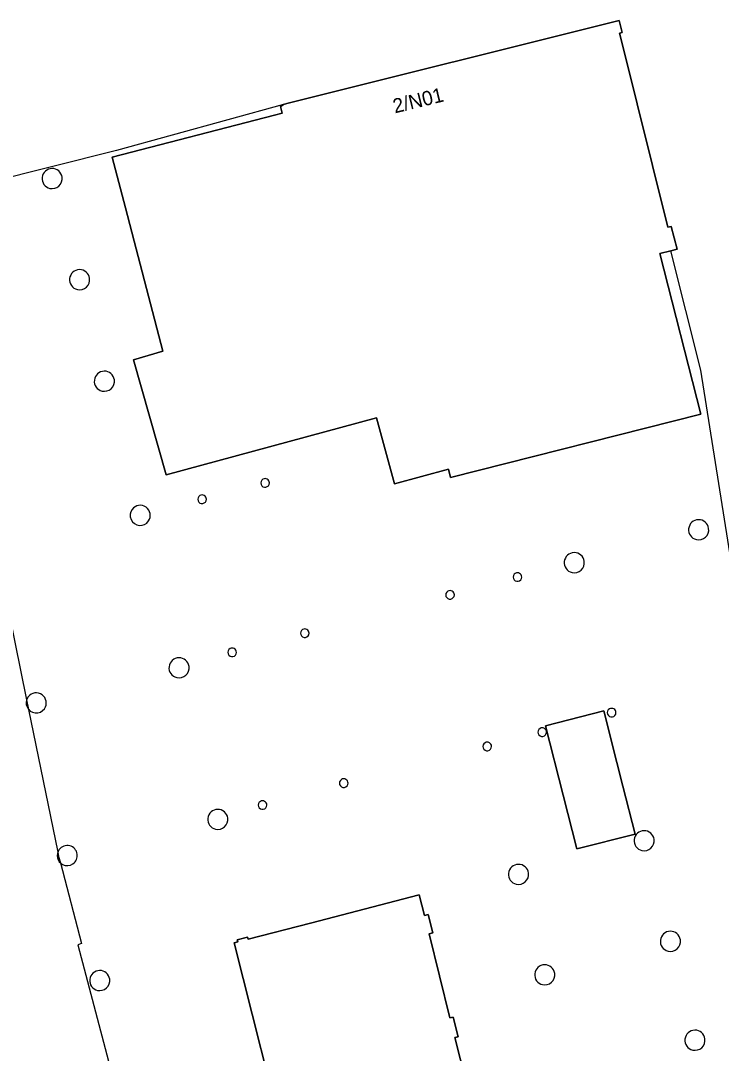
# Model space of a CAD drawing. Extents: x 160806 to 161707, y 383696 to 384148.
# Drawn here: x 161282.3 to 161331, y 383992.9 to 384064.8 of the extents above; entities that cross this region are included whole.
import ezdxf

# ---------------------------------------------------------------- set-up
doc = ezdxf.new("R2010")
doc.units = 0
for name, color, linetype in [('IMGEO_Erf', 7, 'Continuous'), ('IMGEO_Pand', 7, 'Continuous'), ('IMGEO_Pand_nummerreeks', 7, 'Continuous'), ('IMGEO_Pand_overbouw', 7, 'Continuous')]:
    doc.layers.add(name, color=color, linetype=linetype)

msp = doc.modelspace()

# ---------------------------------------------------------------- linework, layer by layer
at = {"layer": 'IMGEO_Erf'}
for points in [[(161329.552, 384037.396), (161312.15, 384032.996), (161312.003, 384033.577), (161308.24, 384032.557), (161306.994, 384037.151), (161292.363, 384033.183), (161290.108, 384041.184), (161292.135, 384041.772), (161290.281, 384048.897), (161289.537, 384051.757), (161288.622, 384055.273), (161299.916, 384058.201), (161300.442, 384058.338), (161300.327, 384058.807), (161300.359, 384058.83), (161300.535, 384058.932), (161300.766, 384059.009), (161323.868, 384064.767), (161324.075, 384063.942), (161323.889, 384063.895), (161324.046, 384063.267), (161327.253, 384050.405), (161327.487, 384050.462), (161327.896, 384048.869), (161327.455, 384048.758), (161326.709, 384048.571)], [(161322.794, 384016.755), (161323.71, 384013.167), (161324.13, 384011.53), (161324.988, 384008.199), (161320.919, 384007.16), (161319.972, 384010.899), (161318.753, 384015.717)], [(161310.919, 384001.335), (161310.658, 384001.268), (161312.108, 383995.404), (161312.338, 383995.464), (161312.682, 383994.096), (161312.451, 383994.037), (161313.62, 383989.378), (161313.677, 383989.154), (161313.593, 383989.134), (161313.129, 383989.019), (161300.843, 383985.84), (161297.111, 384000.629), (161297.354, 384000.692), (161297.319, 384000.838), (161298.032, 384001.03), (161298.073, 384000.878), (161302.412, 384002.002), (161309.96, 384003.959), (161310.329, 384002.536), (161310.591, 384002.604)]]:
    msp.add_lwpolyline(points, close=True, dxfattribs=at)
for centre, radius, start, end in [((161284.444, 384053.784), 0.7, 7.86697, 256.86736), ((161284.444, 384053.785), 0.701, 256.92932, 7.805), ((161286.357, 384046.75), 0.7, 7.89294, 256.84138), ((161286.358, 384046.75), 0.7, 256.81442, 7.91991), ((161288.076, 384039.689), 0.7, 7.86697, 256.86736), ((161288.076, 384039.69), 0.701, 256.92932, 7.805), ((161299.255, 384032.616), 0.3, 119.96327, 360), ((161299.255, 384032.616), 0.3, 359.96327, 119.99999), ((161294.87, 384031.48), 0.3, 119.96327, 0), ((161294.87, 384031.48), 0.3, 359.96327, 119.99999), ((161290.57, 384030.359), 0.7, 326.13202, 143.28729), ((161290.571, 384030.36), 0.7, 143.3683, 326.051), ((161329.397, 384029.359), 0.7, 7.89294, 256.84138), ((161329.398, 384029.359), 0.7, 256.81442, 7.91991), ((161320.751, 384027.07), 0.7, 7.90192, 256.8324), ((161320.752, 384027.07), 0.7, 256.81442, 7.91991), ((161316.8, 384026.069), 0.3, 119.96327, 0), ((161316.8, 384026.069), 0.3, 359.96327, 119.99999), ((161312.11, 384024.832), 0.3, 120.05881, 359.90445), ((161312.11, 384024.831), 0.3, 359.96327, 119.99999), ((161302.012, 384022.167), 0.3, 119.96327, 0), ((161302.012, 384022.167), 0.3, 359.96327, 119.99999), ((161296.962, 384020.834), 0.3, 120.05881, 0.09555), ((161296.962, 384020.834), 0.3, 0.15448, 119.99988), ((161293.268, 384019.76), 0.7, 7.90192, 256.8324), ((161293.269, 384019.76), 0.7, 256.81442, 7.91991), ((161283.338, 384017.319), 0.7, 324.72561, 143.4001), ((161283.338, 384017.319), 0.7, 143.34063, 324.78508), ((161323.346, 384016.638), 0.3, 120.05881, 359.90445), ((161323.346, 384016.637), 0.3, 359.96327, 119.99999), ((161318.518, 384015.284), 0.3, 119.96327, 0), ((161318.518, 384015.284), 0.3, 359.96327, 119.99999), ((161314.695, 384014.29), 0.3, 119.96327, 360), ((161314.695, 384014.29), 0.3, 359.96327, 119.99999), ((161304.717, 384011.737), 0.3, 119.96327, 0), ((161304.717, 384011.737), 0.3, 359.96327, 119.99999), ((161299.072, 384010.212), 0.3, 120.05881, 0.09555), ((161299.072, 384010.211), 0.3, 0.15448, 119.99988), ((161295.966, 384009.215), 0.7, 7.90192, 256.8324), ((161295.967, 384009.215), 0.7, 256.81442, 7.91991), ((161325.608, 384007.732), 0.7, 7.86697, 256.86736), ((161285.493, 384006.7), 0.7, 7.82629, 143.41531), ((161325.608, 384007.733), 0.701, 256.92932, 7.805), ((161285.494, 384006.699), 0.701, 143.41211, 242.01965), ((161285.493, 384006.699), 0.7, 242.05301, 7.90092), ((161316.873, 384005.389), 0.7, 7.86697, 256.86736), ((161316.873, 384005.39), 0.701, 256.92932, 7.805), ((161327.431, 384000.739), 0.7, 7.86697, 256.86736), ((161327.431, 384000.74), 0.701, 256.92932, 7.805), ((161287.757, 383998.008), 0.7, 7.92796, 256.80637), ((161318.696, 383998.405), 0.7, 7.86697, 256.86736), ((161287.757, 383998.009), 0.7, 256.81442, 7.91991), ((161318.696, 383998.406), 0.701, 256.92932, 7.805), ((161329.141, 383993.857), 0.7, 7.89294, 256.84138), ((161329.142, 383993.857), 0.7, 256.81442, 7.91991)]:
    msp.add_arc(centre, radius, start, end, dxfattribs=at)
at = {"layer": 'IMGEO_Pand'}
for points in [[(161327.487, 384050.462), (161327.253, 384050.405), (161324.046, 384063.267), (161323.889, 384063.895), (161324.075, 384063.942), (161323.868, 384064.767), (161300.766, 384059.009), (161300.535, 384058.932), (161300.359, 384058.83), (161300.327, 384058.807), (161300.442, 384058.338), (161299.916, 384058.201), (161288.622, 384055.273), (161289.537, 384051.757), (161290.281, 384048.897), (161292.135, 384041.772), (161290.108, 384041.184), (161292.363, 384033.183), (161306.994, 384037.151), (161308.24, 384032.557), (161312.003, 384033.577), (161312.15, 384032.996), (161329.552, 384037.396), (161326.709, 384048.571), (161327.455, 384048.758), (161327.896, 384048.869)], [(161323.71, 384013.167), (161322.794, 384016.755), (161318.753, 384015.717), (161319.972, 384010.899), (161320.919, 384007.16), (161324.988, 384008.199), (161324.13, 384011.53)], [(161310.658, 384001.268), (161310.919, 384001.335), (161310.591, 384002.604), (161310.329, 384002.536), (161309.96, 384003.959), (161302.412, 384002.002), (161298.073, 384000.878), (161298.032, 384001.03), (161297.319, 384000.838), (161297.354, 384000.692), (161297.111, 384000.629), (161300.843, 383985.84), (161313.129, 383989.019), (161313.593, 383989.134), (161313.677, 383989.154), (161313.62, 383989.378), (161312.451, 383994.037), (161312.682, 383994.096), (161312.338, 383995.464), (161312.108, 383995.404)]]:
    msp.add_lwpolyline(points, close=True, dxfattribs=at)
for centre, radius, start, end in [((161284.444, 384053.784), 0.7, 7.86697, 256.86736), ((161284.444, 384053.785), 0.701, 256.92932, 7.805), ((161286.357, 384046.75), 0.7, 7.89294, 256.84138), ((161286.358, 384046.75), 0.7, 256.81442, 7.91991), ((161288.076, 384039.689), 0.7, 7.86697, 256.86736), ((161288.076, 384039.69), 0.701, 256.92932, 7.805), ((161299.255, 384032.616), 0.3, 119.96327, 360), ((161299.255, 384032.616), 0.3, 359.96327, 119.99999), ((161294.87, 384031.48), 0.3, 119.96327, 0), ((161294.87, 384031.48), 0.3, 359.96327, 119.99999), ((161290.57, 384030.359), 0.7, 326.13202, 143.28729), ((161290.571, 384030.36), 0.7, 143.3683, 326.051), ((161329.397, 384029.359), 0.7, 7.89294, 256.84138), ((161329.398, 384029.359), 0.7, 256.81442, 7.91991), ((161320.751, 384027.07), 0.7, 7.90192, 256.8324), ((161320.752, 384027.07), 0.7, 256.81442, 7.91991), ((161316.8, 384026.069), 0.3, 119.96327, 0), ((161316.8, 384026.069), 0.3, 359.96327, 119.99999), ((161312.11, 384024.832), 0.3, 120.05881, 359.90445), ((161312.11, 384024.831), 0.3, 359.96327, 119.99999), ((161302.012, 384022.167), 0.3, 119.96327, 0), ((161302.012, 384022.167), 0.3, 359.96327, 119.99999), ((161296.962, 384020.834), 0.3, 120.05881, 0.09555), ((161296.962, 384020.834), 0.3, 0.15448, 119.99988), ((161293.268, 384019.76), 0.7, 7.90192, 256.8324), ((161293.269, 384019.76), 0.7, 256.81442, 7.91991), ((161283.338, 384017.319), 0.7, 324.72561, 143.4001), ((161283.338, 384017.319), 0.7, 143.34063, 324.78508), ((161323.346, 384016.638), 0.3, 120.05881, 359.90445), ((161323.346, 384016.637), 0.3, 359.96327, 119.99999), ((161318.518, 384015.284), 0.3, 119.96327, 0), ((161318.518, 384015.284), 0.3, 359.96327, 119.99999), ((161314.695, 384014.29), 0.3, 119.96327, 360), ((161314.695, 384014.29), 0.3, 359.96327, 119.99999), ((161304.717, 384011.737), 0.3, 119.96327, 0), ((161304.717, 384011.737), 0.3, 359.96327, 119.99999), ((161299.072, 384010.212), 0.3, 120.05881, 0.09555), ((161299.072, 384010.211), 0.3, 0.15448, 119.99988), ((161295.966, 384009.215), 0.7, 7.90192, 256.8324), ((161295.967, 384009.215), 0.7, 256.81442, 7.91991), ((161325.608, 384007.732), 0.7, 7.86697, 256.86736), ((161285.493, 384006.7), 0.7, 7.82629, 143.41531), ((161325.608, 384007.733), 0.701, 256.92932, 7.805), ((161285.494, 384006.699), 0.701, 143.41211, 242.01965), ((161285.493, 384006.699), 0.7, 242.05301, 7.90092), ((161316.873, 384005.389), 0.7, 7.86697, 256.86736), ((161316.873, 384005.39), 0.701, 256.92932, 7.805), ((161327.431, 384000.739), 0.7, 7.86697, 256.86736), ((161327.431, 384000.74), 0.701, 256.92932, 7.805), ((161287.757, 383998.008), 0.7, 7.92796, 256.80637), ((161318.696, 383998.405), 0.7, 7.86697, 256.86736), ((161287.757, 383998.009), 0.7, 256.81442, 7.91991), ((161318.696, 383998.406), 0.701, 256.92932, 7.805), ((161329.141, 383993.857), 0.7, 7.89294, 256.84138), ((161329.142, 383993.857), 0.7, 256.81442, 7.91991)]:
    msp.add_arc(centre, radius, start, end, dxfattribs=at)
at = {"layer": 'IMGEO_Pand_overbouw'}
for points in [[(161334.948, 384006.439), (161329.556, 384040.465), (161327.455, 384048.758), (161326.709, 384048.571), (161329.552, 384037.396), (161312.15, 384032.996), (161312.003, 384033.577), (161308.24, 384032.557), (161306.994, 384037.151), (161292.363, 384033.183), (161290.108, 384041.184), (161292.135, 384041.772), (161290.281, 384048.897), (161289.537, 384051.757), (161288.622, 384055.273), (161299.916, 384058.201), (161300.442, 384058.338), (161300.327, 384058.807), (161300.359, 384058.83), (161300.535, 384058.932), (161288.93, 384055.736), (161275.531, 384052.366)], [(161280.625, 384027.497), (161282.668, 384017.523), (161282.801, 384016.859), (161284.836, 384006.941), (161284.897, 384006.643), (161285.017, 384006.185), (161286.486, 384000.594), (161286.226, 384000.503), (161290.822, 383983.081)]]:
    msp.add_lwpolyline(points, dxfattribs=at)

# ---------------------------------------------------------------- texts
at = {"layer": 'IMGEO_Pand_nummerreeks'}
msp.add_text('2/N01', height=1, rotation=13.79682, dxfattribs=at).set_placement((161308.273, 384058.312))

doc.saveas('drawing.dxf')
